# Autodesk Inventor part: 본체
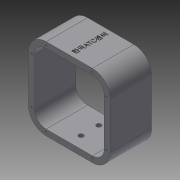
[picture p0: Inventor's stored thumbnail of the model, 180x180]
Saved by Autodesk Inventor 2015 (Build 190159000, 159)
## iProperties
Created: 2016-12
Part Number: 본체
Material: 알루미늄 6061
Document SubType Name: Modeling
Designer: mduedu
Density: 2.71 g/cm^3
Mass: 325.956 g
Surface Area: 772.714 cm^2
Volume: 325.956 cm^3
Appearance: 기본값
Author: mduedu
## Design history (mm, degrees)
sketch "스케치1"
  geometry: L1 (-46, 42)-(-46, -36); L2 (-16, 72)-(62, 72); L3 (92, 42)-(92, -36); L4 (62, -66)-(-16, -66); A1 r 30 centre (-16, -36) between (-46, -36) and (-16, -66); A2 r 30 centre (62, 42) between (92, 42) and (62, 72); A3 r 30 centre (62, -36) between (62, -66) and (92, -36); A4 r 30 centre (-16, 42) between (-16, 72) and (-46, 42); 1 further point
  constraints: 8 end point, 8 point on circle, 8 tangent, 4 centre point, 3 equal radius, 1 horizontal, 1 perpendicular, 1 vertical
  dimensions: "d83" = 30 radius of A2; "d84" = 92 distance from line of L3 point (0, 0); "d85" = 138 distance between parallel lines of L4 L2; "d86" = 46 distance from line of L1 point (0, 0); "d87" = 72 distance from line of point (0, 0) L2
extrude "돌출1" new body sketch "스케치1" stored distance "d3" = 70; taper "d4" = 0 deg
feature "쉘1" dims "d5" = 10
sketch "스케치10"
  geometry: L1 (78, 70)-(0, 70) reference; L2 (-30, 70)-(-30, 0) reference; 4 further points
  constraints: 1 coincident, 1 horizontal alignment, 1 midpoint, 1 vertical alignment, 1 other
  dimensions: "d88" = 35 distance of point (39, 35) point (39, 70) (derived); "d89" = 69 distance from line of point (39, 35) L2 (derived)
feature "엠보싱1" sketch "스케치10" dims "d61" = 0.5, "d62" = 0, "d83" = 30, "d84" = 92, "d85" = 138, "d86" = 46, "d87" = 72
sketch "스케치11"
  geometry: L1 (-36, -36)-(-36, 42) reference; L2 (-16, 62)-(62, 62) reference; L3 (82, 42)-(82, -36) reference; L4 (62, -56)-(-16, -56) reference; L5 (-16, -66)-(62, -66) reference; L6 (92, -36)-(92, 42) reference; L7 (62, 72)-(-16, 72) reference; L8 (-46, 42)-(-46, -36) reference; L9 (-16, 66)-(62, 66); L10 (86, 42)-(86, -36); L11 (62, -60)-(-16, -60); L12 (-40, -36)-(-40, 42); A1 r 20 centre (-16, -36) between (-36, -36) and (-16, -56) reference; A2 r 20 centre (-16, 42) between (-16, 62) and (-36, 42) reference; A3 r 20 centre (62, 42) between (82, 42) and (62, 62) reference; A4 r 20 centre (62, -36) between (62, -56) and (82, -36) reference; A5 r 30 centre (-16, -36) between (-46, -36) and (-16, -66) reference; A6 r 30 centre (62, -36) between (62, -66) and (92, -36) reference; A7 r 30 centre (62, 42) between (92, 42) and (62, 72) reference; A8 r 30 centre (-16, 42) between (-16, 72) and (-46, 42) reference; A9 r 24 centre (62, 42) between (86, 42) and (62, 66); A10 r 24 centre (62, -36) between (62, -60) and (86, -36); A11 r 24 centre (-16, -36) between (-40, -36) and (-16, -60); A12 r 24 centre (-16, 42) between (-16, 66) and (-40, 42); 8 further points
  constraints: 8 coincident, 8 end point, 8 point on circle, 4 centre point, 7 other
  dimensions: "d90" = 6 distance between parallel lines of L9 L7
hole "구멍3" sketch "스케치11" at (-16, 66), (-40, 42), (-40, -36), (-16, -60), (62, -60), (86, -36), (86, 42), (62, 66) diameter "d63" = 3.242; stored, may be unused: countersink angle "d67" = 90 deg, drill point angle "d69" = 120 deg; dims "d64" = 8.6, "d65" = 4, "d66" = 2, "d68" = 10.6
sketch "스케치12"
  geometry: L1 (16, -56)-(-62, -56) reference; L2 (-82, -36)-(-82, 42) reference; L3 (-62, 62)-(16, 62) reference; L4 (36, 42)-(36, -36) reference; L5 (46, -36)-(46, 42) reference; L6 (16, 72)-(-62, 72) reference; L7 (-92, 42)-(-92, -36) reference; L8 (-62, -66)-(16, -66) reference; L9 (-62, 66)-(16, 66); L10 (40, 42)-(40, -36); L11 (16, -60)-(-62, -60); L12 (-86, -36)-(-86, 42); A1 r 20 centre (16, -36) between (16, -56) and (36, -36) reference; A2 r 20 centre (-62, -36) between (-82, -36) and (-62, -56) reference; A3 r 20 centre (-62, 42) between (-62, 62) and (-82, 42) reference; A4 r 20 centre (16, 42) between (36, 42) and (16, 62) reference; A5 r 30 centre (16, -36) between (16, -66) and (46, -36) reference; A6 r 30 centre (16, 42) between (46, 42) and (16, 72) reference; A7 r 30 centre (-62, 42) between (-62, 72) and (-92, 42) reference; A8 r 30 centre (-62, -36) between (-92, -36) and (-62, -66) reference; A9 r 24 centre (16, 42) between (40, 42) and (16, 66); A10 r 24 centre (16, -36) between (16, -60) and (40, -36); A11 r 24 centre (-62, -36) between (-86, -36) and (-62, -60); A12 r 24 centre (-62, 42) between (-62, 66) and (-86, 42); 8 further points
  constraints: 8 coincident, 8 end point, 8 point on circle, 4 centre point, 7 other
  dimensions: "d91" = 6 distance between parallel lines of L9 L6
hole "구멍5" sketch "스케치12" at (-62, 66), (-86, 42), (-86, -36), (-62, -60), (16, -60), (40, -36), (40, 42), (16, 66) diameter "d70" = 3.242; stored, may be unused: countersink angle "d74" = 90 deg, drill point angle "d76" = 120 deg; dims "d71" = 8.6, "d72" = 4, "d73" = 2, "d75" = 10.6
sketch "스케치15"
  geometry: L1 (135.6, -35)-(-57.6, -35) reference; L2 (78, 0)-(0, 0) reference; L3 (0, -70)-(78, -70) reference; L4 (39, 0)-(39, -70); C1 r 4 at (39, -20); C2 r 4 at (39, -50); 1 further point
  constraints: 2 centre point, 2 end point, 2 midpoint, 1 point on line, 1 symmetric about line, 1 other
  dimensions: "d92" = 8 diameter of C1; "d93" = 15 distance from line of C1.centre L1
extrude "돌출6" cut sketch "스케치15" stored distance "d94" = 10; taper "d95" = 0 deg
node "솔리드1"
node "투영된 루프3"
node "투영된 루프4"
